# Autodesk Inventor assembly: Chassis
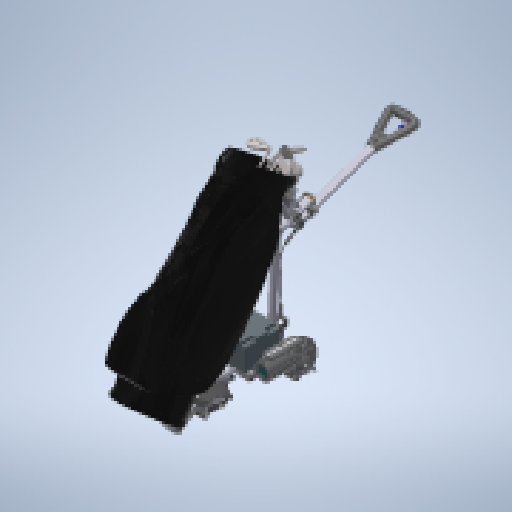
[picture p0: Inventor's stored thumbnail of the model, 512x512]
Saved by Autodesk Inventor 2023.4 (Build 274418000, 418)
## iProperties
Created: 2011-01
Part Number: Chassis
Document SubType Name: Assembly
Designer: eric
Mass: 6282.54 g
Surface Area: 19237.8 cm^2
Volume: 6282.54 cm^3
Density: 1 g/cm^3
Author: eric
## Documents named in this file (33)
- C:\Users\bruno\Documents\1-Cours-2024-25\TSsI\7-Dynamique\chariot de golf\chariot_de_golf\chariot_de_golf_trolem\Chassis.iam
- C:\Users\bruno\Documents\1-Cours-2024-25\TSsI\7-Dynamique\chariot de golf\chariot_de_golf\chariot_de_golf_trolem\59batterie_Defaut.ipt
- C:\Users\bruno\Documents\1-Cours-2024-25\TSsI\7-Dynamique\chariot de golf\chariot_de_golf\chariot_de_golf_trolem\montage1chassis_Defaut.iam
- C:\Users\bruno\Documents\1-Cours-2024-25\TSsI\7-Dynamique\chariot de golf\chariot_de_golf\chariot_de_golf_trolem\40Enjoliveur_M8_Defaut.ipt
- C:\Users\bruno\Documents\1-Cours-2024-25\TSsI\7-Dynamique\chariot de golf\chariot_de_golf\chariot_de_golf_trolem\5.1Vis CBLX M8-55.ipt
- C:\Users\bruno\Documents\1-Cours-2024-25\TSsI\7-Dynamique\chariot de golf\chariot_de_golf\chariot_de_golf_trolem\5.1cache-ecrouM10_Defaut.ipt
- C:\Users\bruno\Documents\1-Cours-2024-25\TSsI\7-Dynamique\chariot de golf\chariot_de_golf\chariot_de_golf_trolem\montage2timon_Defaut.iam
- C:\Users\bruno\Documents\1-Cours-2024-25\TSsI\7-Dynamique\chariot de golf\chariot_de_golf\chariot_de_golf_trolem\montage4tube_alu_Defaut.iam
- C:\Users\bruno\Documents\1-Cours-2024-25\TSsI\7-Dynamique\chariot de golf\chariot_de_golf\chariot_de_golf_trolem\montage_6cable_Defaut.iam
- C:\Users\bruno\Documents\1-Cours-2024-25\TSsI\7-Dynamique\chariot de golf\chariot_de_golf\chariot_de_golf_trolem\44Rondelle_M8_Defaut.ipt
- C:\Users\bruno\Documents\1-Cours-2024-25\TSsI\7-Dynamique\chariot de golf\chariot_de_golf\chariot_de_golf_trolem\33vis M6_60.ipt
- C:\Users\bruno\Documents\1-Cours-2024-25\TSsI\7-Dynamique\chariot de golf\chariot_de_golf\chariot_de_golf_trolem\32vis M8_60.ipt
- C:\Users\bruno\Documents\1-Cours-2024-25\TSsI\7-Dynamique\chariot de golf\chariot_de_golf\chariot_de_golf_trolem\39Ecrou H_ FR_ M8.ipt
- C:\Users\bruno\Documents\1-Cours-2024-25\TSsI\7-Dynamique\chariot de golf\chariot_de_golf\chariot_de_golf_trolem\35Vis_CBLZ_M6_55.ipt
- C:\Users\bruno\Documents\1-Cours-2024-25\TSsI\7-Dynamique\chariot de golf\chariot_de_golf\chariot_de_golf_trolem\36Ecrou H_ FR_ M6.ipt
- C:\Users\bruno\Documents\1-Cours-2024-25\TSsI\7-Dynamique\chariot de golf\chariot_de_golf\chariot_de_golf_trolem\30Ressort_e1.5_Defaut.ipt
- C:\Users\bruno\Documents\1-Cours-2024-25\TSsI\7-Dynamique\chariot de golf\chariot_de_golf\chariot_de_golf_trolem\5.1 ressort_Defaut.ipt
- C:\Users\bruno\Documents\1-Cours-2024-25\TSsI\7-Dynamique\chariot de golf\chariot_de_golf\chariot_de_golf_trolem\5.1Vis CBLX M8-45.ipt
- C:\Users\bruno\Documents\1-Cours-2024-25\TSsI\7-Dynamique\chariot de golf\chariot_de_golf\chariot_de_golf_trolem\39Ecrou H_FR_ M8.ipt
- C:\Users\bruno\Documents\1-Cours-2024-25\TSsI\7-Dynamique\chariot de golf\chariot_de_golf\chariot_de_golf_trolem\5.1rondelle plastique e8,5x2_Defaut.ipt
- C:\Users\bruno\Documents\1-Cours-2024-25\TSsI\7-Dynamique\chariot de golf\chariot_de_golf\chariot_de_golf_trolem\5.1carre_monte_Defaut.iam
- C:\Users\bruno\Documents\1-Cours-2024-25\TSsI\7-Dynamique\chariot de golf\chariot_de_golf\chariot_de_golf_trolem\70Rondelle_M10_Defaut.ipt
- C:\Users\bruno\Documents\1-Cours-2024-25\TSsI\7-Dynamique\chariot de golf\chariot_de_golf\chariot_de_golf_trolem\5.1Ecrou freine M 10.ipt
- C:\Users\bruno\Documents\1-Cours-2024-25\TSsI\7-Dynamique\chariot de golf\chariot_de_golf\chariot_de_golf_trolem\5.1Rondelle_e8_Defaut.ipt
- C:\Users\bruno\Documents\1-Cours-2024-25\TSsI\7-Dynamique\chariot de golf\chariot_de_golf\chariot_de_golf_trolem\68protection_roues_Defaut.ipt
- C:\Users\bruno\Documents\1-Cours-2024-25\TSsI\7-Dynamique\chariot de golf\chariot_de_golf\chariot_de_golf_trolem\38Rondelle plate_M8.ipt
- C:\Users\bruno\Documents\1-Cours-2024-25\TSsI\7-Dynamique\chariot de golf\chariot_de_golf\chariot_de_golf_trolem\69VisHM8_100_Defaut.ipt
- C:\Users\bruno\Documents\1-Cours-2024-25\TSsI\7-Dynamique\chariot de golf\chariot_de_golf\chariot_de_golf_trolem\12motoreducteur_Defaut.iam
- C:\Users\bruno\Documents\1-Cours-2024-25\TSsI\7-Dynamique\chariot de golf\chariot_de_golf\chariot_de_golf_trolem\5.1support_roue_monte_Defaut.iam
- C:\Users\bruno\Documents\1-Cours-2024-25\TSsI\7-Dynamique\chariot de golf\chariot_de_golf\chariot_de_golf_trolem\sac.ipt
- C:\Users\bruno\Documents\1-Cours-2024-25\TSsI\7-Dynamique\chariot de golf\chariot_de_golf\chariot_de_golf_trolem\Sac-golf\Golfbag_4.ipt
- C:\Users\bruno\Documents\1-Cours-2024-25\TSsI\7-Dynamique\chariot de golf\chariot_de_golf\chariot_de_golf_trolem\Sac-golf\Club5.ipt
- C:\Users\bruno\Documents\1-Cours-2024-25\TSsI\7-Dynamique\chariot de golf\chariot_de_golf\chariot_de_golf_trolem\Sac-golf\Club7.ipt
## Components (55 placed, 32 different names)
1. 5.1support_roue_monte_Defaut:1 [sub-assembly]
2. 12motoreducteur_Defaut:1 [sub-assembly]
3. 35Vis_CBLZ_M6_55:2
4. 35Vis_CBLZ_M6_55:4
5. 35Vis_CBLZ_M6_55:3
6. 36Ecrou H_ FR_ M6:3
7. 36Ecrou H_ FR_ M6:4
8. 36Ecrou H_ FR_ M6:5
9. 36Ecrou H_ FR_ M6:2
10. 70Rondelle_M10_Defaut:3
11. 70Rondelle_M10_Defaut:4
12. 70Rondelle_M10_Defaut:5
13. 70Rondelle_M10_Defaut:2
14. 38Rondelle plate_M8:4
15. 38Rondelle plate_M8:5
16. 69VisHM8_100_Defaut:1
17. 38Rondelle plate_M8:1
18. 38Rondelle plate_M8:2
19. 38Rondelle plate_M8:3
20. 39Ecrou H_ FR_ M8:3
21. 68protection_roues_Defaut:1
22. 39Ecrou H_ FR_ M8:2
23. 5.1Rondelle_e8_Defaut:1
24. 5.1rondelle plastique e8,5x2_Defaut:3
25. 5.1Ecrou freine M 10:1
26. 70Rondelle_M10_Defaut:1
27. 5.1carre_monte_Defaut:1 [sub-assembly]
28. 5.1rondelle plastique e8,5x2_Defaut:1
29. 5.1rondelle plastique e8,5x2_Defaut:2
30. 39Ecrou H_FR_ M8:1
31. 5.1Vis CBLX M8-45:1
32. 5.1 ressort_Defaut:1
33. 35Vis_CBLZ_M6_55:1
34. 44Rondelle_M8_Defaut:2
35. 30Ressort_e1.5_Defaut:1
36. 33vis M6_60:1
37. 32vis M8_60:1
38. 44Rondelle_M8_Defaut:1
39. 39Ecrou H_ FR_ M8:1
40. 36Ecrou H_ FR_ M6:1
41. montage2timon_Defaut:1 [sub-assembly]
42. montage_6cable_Defaut:1 [sub-assembly]
43. montage4tube_alu_Defaut:1 [sub-assembly]
44. 5.1Vis CBLX M8-55:1
45. 5.1cache-ecrouM10_Defaut:1
46. 40Enjoliveur_M8_Defaut:1
47. montage1chassis_Defaut:1 [sub-assembly]
48. 59batterie_Defaut:1
49. sac:1
50. Golfbag_4:1 — Placage:1, Placage:2
51. Club5:1 — Placage:1, Placage:3, Placage:5
52. Club7:1 — Placage:2, Placage:4
53. Club7:2 — Placage:5
54. Club5:2 — Placage:3
55. Club5:3 — Placage:4
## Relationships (5: Mate 5)
- Placage:1 [Mate]: Golfbag_4:1 ↔ Club5:1
- Placage:2 [Mate]: Golfbag_4:1 ↔ Club7:1
- Placage:3 [Mate]: Club5:1 ↔ Club5:2
- Placage:4 [Mate]: Club7:1 ↔ Club5:3
- Placage:5 [Mate]: Club5:1 ↔ Club7:2
